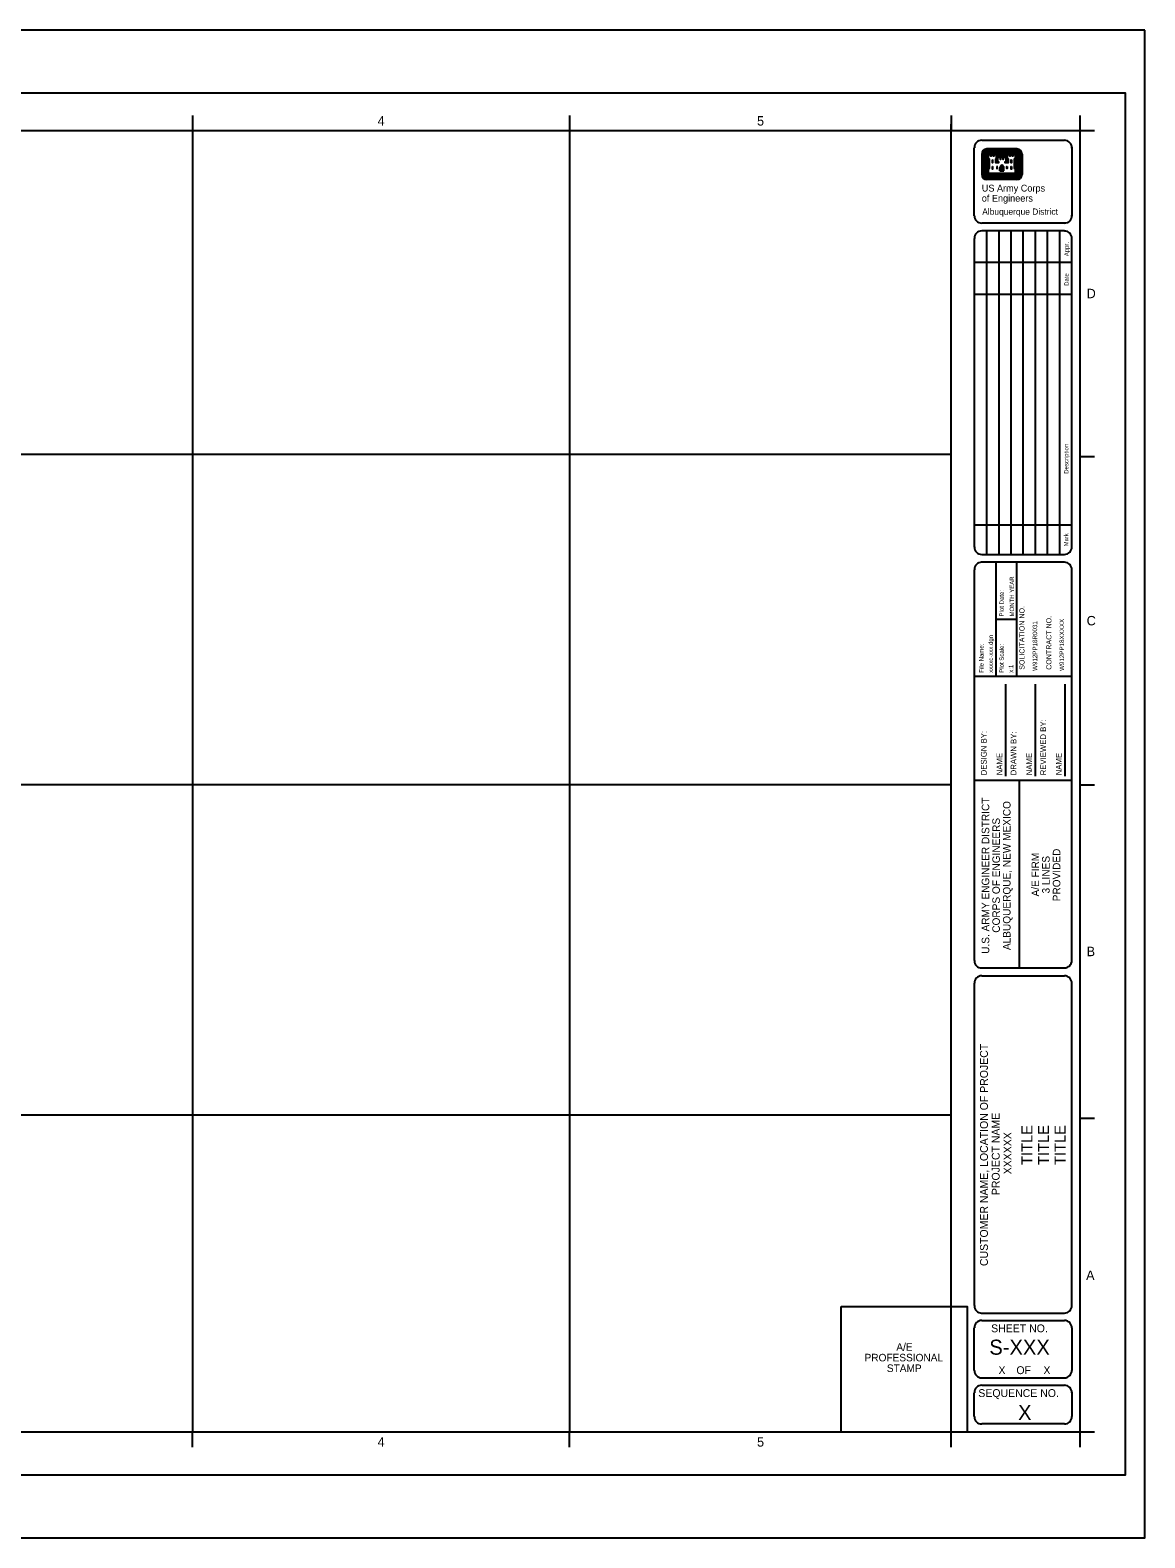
# Model space of a CAD drawing. Extents: x -0.19 to 2.81, y 0.03 to 2.03.
# Drawn here: x 1.329 to 2.806, y 0.032 to 2.032 of the extents above; entities that cross this region are included whole.
import ezdxf

# ---------------------------------------------------------------- set-up
doc = ezdxf.new("R2010")
doc.units = 0
for name, color, linetype in [('G-ANNO-NPLT', 7, 'Continuous'), ('G-ANNO-SYMB', 7, 'Continuous'), ('G-ANNO-TEXT', 7, 'Continuous'), ('G-ANNO-TTBL', 7, 'Continuous'), ('S-ANNO-TEXT', 7, 'Continuous')]:
    doc.layers.add(name, color=color, linetype=linetype)

msp = doc.modelspace()

# ---------------------------------------------------------------- linework, layer by layer
at = {"layer": 'G-ANNO-NPLT'}
for p, q in [((2.5495, 0.1551), (2.5495, 1.9077)), ((1.5442, 1.8993), (1.5442, 0.1724)), ((2.0436, 1.8993), (2.0436, 0.1724)), ((2.5495, 1.4696), (0.0565, 1.4696)), ((2.5495, 1.0314), (0.0565, 1.0314)), ((2.5495, 0.5933), (0.0565, 0.5933))]:
    msp.add_line(p, q, dxfattribs=at)
at = {"layer": 'G-ANNO-SYMB'}
for p, q in [((2.5903, 1.8679), (2.5903, 1.841)), ((2.5906, 1.8679), (2.5906, 1.841)), ((2.5913, 1.8679), (2.5913, 1.841)), ((2.5919, 1.8679), (2.5919, 1.841)), ((2.5923, 1.8679), (2.5923, 1.841)), ((2.5946, 1.8679), (2.5946, 1.841)), ((2.5952, 1.8679), (2.5952, 1.841)), ((2.5959, 1.8679), (2.5959, 1.841)), ((2.5962, 1.8679), (2.5962, 1.841)), ((2.5969, 1.8679), (2.5969, 1.841)), ((2.6366, 1.8748), (2.5972, 1.8748)), ((2.6366, 1.8744), (2.5972, 1.8744)), ((2.6366, 1.8738), (2.5972, 1.8738)), ((2.6366, 1.8731), (2.5972, 1.8731)), ((2.6366, 1.8728), (2.5972, 1.8728)), ((2.6366, 1.8705), (2.5972, 1.8705)), ((2.6366, 1.8698), (2.5972, 1.8698)), ((2.6366, 1.8692), (2.5972, 1.8692)), ((2.6366, 1.8689), (2.5972, 1.8689)), ((2.6366, 1.8682), (2.5972, 1.8682)), ((2.5975, 1.8679), (2.5975, 1.8413)), ((2.5978, 1.8679), (2.5978, 1.842)), ((2.5985, 1.862), (2.5985, 1.8485)), ((2.5991, 1.8616), (2.5991, 1.8492)), ((2.611, 1.8675), (2.6231, 1.8675)), ((2.611, 1.8672), (2.6231, 1.8672)), ((2.611, 1.8666), (2.6231, 1.8666)), ((2.611, 1.8659), (2.6231, 1.8659)), ((2.611, 1.8653), (2.6231, 1.8653)), ((2.611, 1.8649), (2.6231, 1.8649)), ((2.611, 1.8643), (2.6231, 1.8643)), ((2.6349, 1.8616), (2.6349, 1.8492)), ((2.6352, 1.862), (2.6352, 1.8485)), ((2.6359, 1.8679), (2.6359, 1.842)), ((2.6366, 1.8679), (2.6366, 1.8413)), ((2.6369, 1.8679), (2.6369, 1.841)), ((2.6375, 1.8679), (2.6375, 1.841)), ((2.6382, 1.8679), (2.6382, 1.841)), ((2.6385, 1.8679), (2.6385, 1.841)), ((2.6392, 1.8679), (2.6392, 1.841)), ((2.6415, 1.8679), (2.6415, 1.841)), ((2.6421, 1.8679), (2.6421, 1.841)), ((2.6428, 1.8679), (2.6428, 1.841)), ((2.6431, 1.8679), (2.6431, 1.841)), ((2.6438, 1.8679), (2.6438, 1.841)), ((2.6366, 1.8406), (2.5972, 1.8406)), ((2.6366, 1.8403), (2.5972, 1.8403)), ((2.6366, 1.8413), (2.5975, 1.8413)), ((2.6359, 1.842), (2.5978, 1.842)), ((2.6142, 1.8459), (2.6142, 1.8502)), ((2.6142, 1.8459), (2.6195, 1.8459)), ((2.6149, 1.8459), (2.6149, 1.8502)), ((2.6156, 1.8459), (2.6156, 1.8502)), ((2.6159, 1.8459), (2.6159, 1.8502)), ((2.6165, 1.8459), (2.6165, 1.8502)), ((2.6172, 1.8459), (2.6172, 1.8502)), ((2.6179, 1.8459), (2.6179, 1.8502)), ((2.6185, 1.8459), (2.6185, 1.8502)), ((2.6188, 1.8459), (2.6188, 1.8502)), ((2.6195, 1.8459), (2.6195, 1.8502)), ((2.6366, 1.8397), (2.5972, 1.8397)), ((2.6366, 1.839), (2.5972, 1.839)), ((2.6366, 1.8383), (2.5972, 1.8383)), ((2.6366, 1.836), (2.5972, 1.836)), ((2.6366, 1.8357), (2.5972, 1.8357)), ((2.6366, 1.8351), (2.5972, 1.8351)), ((2.6366, 1.8344), (2.5972, 1.8344)), ((2.6366, 1.8341), (2.5972, 1.8341))]:
    msp.add_line(p, q, dxfattribs=at)
for points in [[(2.5985, 1.8679), (2.5985, 1.8626), (2.5995, 1.8616), (2.5995, 1.8492), (2.5985, 1.8479), (2.5985, 1.8423), (2.6356, 1.8423), (2.6356, 1.8479), (2.6343, 1.8492), (2.6343, 1.8616), (2.6356, 1.8626), (2.6356, 1.8679), (2.6306, 1.8679), (2.6267, 1.8679), (2.6234, 1.8679), (2.6234, 1.8626), (2.6244, 1.8616), (2.6244, 1.857), (2.6218, 1.857), (2.6218, 1.8574), (2.6231, 1.8587), (2.6231, 1.8636), (2.6182, 1.8636), (2.6142, 1.8636), (2.611, 1.8636), (2.611, 1.8587), (2.6119, 1.8574), (2.6119, 1.857), (2.6093, 1.857), (2.6093, 1.8616), (2.6106, 1.8626), (2.6106, 1.8679), (2.6057, 1.8679), (2.6018, 1.8679), (2.5985, 1.8679)], [(2.5988, 1.8672), (2.5988, 1.863), (2.6001, 1.8616), (2.6001, 1.8488), (2.5988, 1.8479), (2.5988, 1.8429), (2.6349, 1.8429), (2.6349, 1.8479), (2.6336, 1.8488), (2.6336, 1.8616), (2.6349, 1.863), (2.6349, 1.8672), (2.6313, 1.8672), (2.6313, 1.8653), (2.631, 1.8653), (2.631, 1.8672), (2.6277, 1.8672), (2.6277, 1.8653), (2.6274, 1.8653), (2.6274, 1.8672), (2.6241, 1.8672), (2.6241, 1.863), (2.6251, 1.8616), (2.6251, 1.8564), (2.6211, 1.8564), (2.6211, 1.8577), (2.6224, 1.8587), (2.6224, 1.8633), (2.6188, 1.8633), (2.6188, 1.861), (2.6185, 1.861), (2.6185, 1.8633), (2.6152, 1.8633), (2.6152, 1.861), (2.6149, 1.861), (2.6149, 1.8633), (2.6113, 1.8633), (2.6113, 1.8587), (2.6126, 1.8577), (2.6126, 1.8564), (2.6087, 1.8564), (2.6087, 1.8616), (2.61, 1.863), (2.61, 1.8672), (2.6064, 1.8672), (2.6064, 1.8653), (2.606, 1.8653), (2.606, 1.8672), (2.6028, 1.8672), (2.6028, 1.8653), (2.6024, 1.8653), (2.6024, 1.8672), (2.5988, 1.8672)], [(2.6044, 1.8603), (2.6044, 1.8564), (2.6047, 1.8564), (2.6047, 1.8603), (2.6044, 1.8603)], [(2.6103, 1.8616), (2.61, 1.8613), (2.61, 1.8577), (2.611, 1.8577), (2.6103, 1.8584), (2.6103, 1.8616)], [(2.6238, 1.8616), (2.6241, 1.8613), (2.6241, 1.8577), (2.6228, 1.8577), (2.6234, 1.8584), (2.6234, 1.8616)], [(2.6297, 1.8603), (2.6297, 1.8564), (2.6293, 1.8564), (2.6293, 1.8603), (2.6297, 1.8603)], [(2.6044, 1.8515), (2.6044, 1.8479), (2.6047, 1.8479), (2.6047, 1.8515), (2.6044, 1.8515)], [(2.6103, 1.8515), (2.6103, 1.8488), (2.6106, 1.8488), (2.6106, 1.8515), (2.6103, 1.8515)], [(2.6238, 1.8515), (2.6238, 1.8488), (2.6234, 1.8488), (2.6234, 1.8515), (2.6238, 1.8515)], [(2.6297, 1.8515), (2.6297, 1.8479), (2.6293, 1.8479), (2.6293, 1.8515), (2.6297, 1.8515)]]:
    msp.add_lwpolyline(points, dxfattribs=at)
for centre, radius, start, end in [((2.5972, 1.8678), 0.00696, 90, 180), ((2.5972, 1.8678), 0.00656, 90, 180), ((2.5972, 1.8678), 0.006, 90, 180), ((2.5972, 1.8678), 0.00543, 90, 180), ((2.5972, 1.8678), 0.00487, 90, 180), ((2.5972, 1.8678), 0.00261, 90, 180), ((2.5972, 1.8678), 0.00205, 90, 180), ((2.5972, 1.8678), 0.00148, 90, 180), ((2.5972, 1.8678), 0.000919, 90, 180), ((2.5972, 1.8678), 0.000355, 90, 180), ((2.6367, 1.8678), 0.00696, 0, 90), ((2.6367, 1.8678), 0.00656, 0, 90), ((2.6367, 1.8678), 0.006, 0, 90), ((2.6367, 1.8678), 0.00543, 0, 90), ((2.6367, 1.8678), 0.00487, 0, 90), ((2.6367, 1.8678), 0.00261, 0, 90), ((2.6367, 1.8678), 0.00205, 0, 90), ((2.6367, 1.8678), 0.00148, 0, 90), ((2.6367, 1.8678), 0.000919, 0, 90), ((2.6367, 1.8678), 0.000355, 0, 90), ((2.5972, 1.8411), 0.00696, 180, 270), ((2.5972, 1.8411), 0.00656, 180, 270), ((2.5972, 1.8411), 0.006, 180, 270), ((2.5972, 1.8411), 0.00543, 180, 270), ((2.5972, 1.8411), 0.00487, 180, 270), ((2.5972, 1.8411), 0.00261, 180, 270), ((2.5972, 1.8411), 0.00205, 180, 270), ((2.5972, 1.8411), 0.00148, 180, 270), ((2.5972, 1.8411), 0.000919, 180, 270), ((2.5972, 1.8411), 0.000355, 180, 270), ((2.6179, 1.8498), 0.00361, 105.6681, 176.0575), ((2.6179, 1.8498), 0.00305, 103.4698, 176.0575), ((2.6179, 1.8498), 0.00248, 103.4698, 176.0575), ((2.6179, 1.8498), 0.00192, 103.4698, 176.0575), ((2.616, 1.8498), 0.00135, 3.9425, 76.5302), ((2.616, 1.8498), 0.00192, 3.9425, 76.5302), ((2.616, 1.8498), 0.00248, 3.9425, 76.5302), ((2.6179, 1.8498), 0.00135, 103.4698, 176.0575), ((2.616, 1.8498), 0.00305, 3.9425, 76.5302), ((2.616, 1.8498), 0.00361, 3.9425, 74.3949), ((2.6367, 1.8411), 0.00696, 270, 0), ((2.6367, 1.8411), 0.00261, 270, 0), ((2.6367, 1.8411), 0.00205, 270, 0), ((2.6367, 1.8411), 0.00148, 270, 0), ((2.6367, 1.8411), 0.000919, 270, 0), ((2.6367, 1.8411), 0.000355, 270, 0), ((2.6367, 1.8411), 0.00487, 270, 360), ((2.6367, 1.8411), 0.00543, 270, 360), ((2.6367, 1.8411), 0.006, 270, 360), ((2.6367, 1.8411), 0.00656, 270, 360)]:
    msp.add_arc(centre, radius, start, end, dxfattribs=at)
at = {"layer": 'G-ANNO-TEXT'}
msp.add_line((2.6362, 1.2506), (2.609, 1.2506), dxfattribs=at)
at = {"layer": 'G-ANNO-TTBL'}
for p, q in [((1.5442, 1.919), (1.5442, 1.8993)), ((2.0436, 1.919), (2.0436, 1.8993)), ((2.5495, 1.919), (2.5495, 1.8993)), ((2.7202, 1.919), (2.7202, 0.1527)), ((0.0368, 1.8993), (2.7398, 1.8993)), ((2.5804, 1.7247), (2.7097, 1.7247)), ((2.5804, 1.682), (2.7097, 1.682)), ((2.7202, 1.4667), (2.7398, 1.4667)), ((2.5804, 1.3763), (2.7097, 1.3763)), ((2.609, 1.3265), (2.609, 1.1751)), ((2.6362, 1.3265), (2.6362, 1.1751)), ((2.7097, 1.1751), (2.5804, 1.1751)), ((2.6221, 1.0428), (2.6221, 1.1647)), ((2.6614, 1.0428), (2.6614, 1.1647)), ((2.7008, 1.0428), (2.7008, 1.1647)), ((2.7097, 1.0371), (2.5804, 1.0371)), ((2.6399, 1.0371), (2.6399, 0.7884)), ((2.7202, 1.0314), (2.7398, 1.0314)), ((2.7202, 0.5891), (2.7398, 0.5891)), ((2.7398, 0.1724), (0.0368, 0.1724)), ((1.5442, 0.1527), (1.5442, 0.1724)), ((2.0436, 0.1527), (2.0436, 0.1724)), ((2.5495, 0.1527), (2.5495, 0.1724))]:
    msp.add_line(p, q, dxfattribs=at)
for points in [[(2.8064, 2.0324), (-0.1936, 2.0324), (-0.1936, 0.0324), (2.8064, 0.0324)], [(-0.053, 1.9491), (2.7804, 1.9491), (2.7804, 0.1157), (-0.053, 0.1157)], [(2.4041, 0.3391), (2.5708, 0.3391), (2.5708, 0.1724), (2.4041, 0.1724)]]:
    msp.add_lwpolyline(points, close=True, dxfattribs=at)
for points in [[(2.5903, 1.8863), (2.6999, 1.8863)], [(2.5804, 1.7863), (2.5804, 1.8764)], [(2.7097, 1.877), (2.7097, 1.7857)], [(2.7006, 1.7765), (2.5903, 1.7765)], [(2.6999, 1.7661), (2.5903, 1.7661)], [(2.5966, 1.7661), (2.5966, 1.3369)], [(2.6127, 1.7661), (2.6127, 1.3369)], [(2.6288, 1.7661), (2.6288, 1.3369)], [(2.6449, 1.7661), (2.6449, 1.3369)], [(2.661, 1.7661), (2.661, 1.3369)], [(2.6771, 1.7661), (2.6771, 1.3369)], [(2.6932, 1.7661), (2.6932, 1.3369)], [(2.5804, 1.7562), (2.5804, 1.3467)], [(2.7097, 1.3461), (2.7097, 1.7562)], [(2.6999, 1.3265), (2.5894, 1.3265)], [(2.5903, 1.3369), (2.6999, 1.3369)], [(2.5804, 1.3167), (2.5804, 0.7982)], [(2.7097, 0.7982), (2.7097, 1.3167)], [(2.5903, 0.7884), (2.6999, 0.7884)], [(2.5804, 0.7681), (2.5804, 0.3404)], [(2.5903, 0.778), (2.6999, 0.778)], [(2.7097, 0.3408), (2.7097, 0.7681)], [(2.5896, 0.3306), (2.6999, 0.3306)], [(2.5903, 0.3207), (2.6999, 0.3207)], [(2.5804, 0.2545), (2.5804, 0.3109)], [(2.7097, 0.3109), (2.7097, 0.2545)], [(2.5903, 0.2446), (2.6999, 0.2446)], [(2.5804, 0.1933), (2.5804, 0.2249)], [(2.5903, 0.2348), (2.6999, 0.2348)], [(2.7097, 0.2255), (2.7097, 0.1933)], [(2.6999, 0.1835), (2.5903, 0.1835)]]:
    msp.add_lwpolyline(points, dxfattribs=at)
for centre, start, end in [((2.5903, 1.8764), 90, 180), ((2.6999, 1.8764), 356.3757, 90), ((2.5903, 1.7863), 180, 270), ((2.6999, 1.7863), 270, 3.6243), ((2.5903, 1.7562), 90, 180), ((2.6999, 1.7561), 0, 90), ((2.5903, 1.3468), 180, 270), ((2.6999, 1.3467), 270, 0), ((2.5903, 1.3167), 90, 180), ((2.6999, 1.3167), 0, 90), ((2.5903, 0.7982), 180, 270), ((2.6999, 0.7983), 270, 0), ((2.5903, 0.7681), 90, 180), ((2.6999, 0.7681), 0, 90), ((2.5903, 0.3404), 180, 270), ((2.6999, 0.3404), 270, 0), ((2.5903, 0.3109), 90, 180), ((2.6999, 0.3109), 0, 90), ((2.5903, 0.2545), 180, 270), ((2.6999, 0.2545), 270, 0), ((2.5903, 0.2249), 90, 180), ((2.6999, 0.2249), 0, 90), ((2.5903, 0.1933), 180, 270), ((2.6999, 0.1933), 270, 0)]:
    msp.add_arc(centre, 0.00984, start, end, dxfattribs=at)
at = {"layer": 'S-ANNO-TEXT'}
msp.add_circle((2.7804, 0.1157), 0.0000168, dxfattribs=at)

# ---------------------------------------------------------------- texts
at = {"layer": 'G-ANNO-TEXT'}
for s, height, p in [('4', 0.0125, (1.7894, 1.9058)), ('5', 0.0125, (2.2924, 1.9058)), ('US Army Corps', 0.009029, (2.5903, 1.8183)), ('of Engineers', 0.009029, (2.5903, 1.8049)), ('Albuquerque District', 0.00833, (2.5909, 1.7875)), ('D', 0.0125, (2.7293, 1.6768)), ('C', 0.0125, (2.7293, 1.2428)), ('B', 0.0125, (2.7293, 0.804)), ('A', 0.0125, (2.7286, 0.3745)), ('SHEET NO.', 0.01042, (2.6027, 0.3051)), ('A/E ', 0.01, (2.477, 0.2806)), ('PROFESSIONAL', 0.01, (2.4349, 0.2665)), ('STAMP', 0.01, (2.4645, 0.2524)), ('OF', 0.01042, (2.6362, 0.2496)), ('SEQUENCE NO.', 0.010417, (2.5857, 0.2192)), ('4', 0.0125, (1.7894, 0.1534)), ('5', 0.0125, (2.2924, 0.1534))]:
    msp.add_text(s, height=height, dxfattribs=at).set_placement(p)
for s, height, p in [('Appr.', 0.00574, (2.7055, 1.7325)), ('Date', 0.00574, (2.7055, 1.6932)), ('Description', 0.005741, (2.7051, 1.4439)), ('Mark', 0.00558, (2.7048, 1.3478)), ('MONTH YEAR', 0.00578, (2.6331, 1.2546)), ('Plot Date:', 0.00579, (2.6195, 1.2546)), ('SOLICITATION NO.', 0.006809, (2.6469, 1.1839)), ('W912PP18R0031', 0.005968, (2.6637, 1.1824)), ('CONTRACT NO.', 0.006809, (2.6826, 1.1839)), ('W912PP18XXXXX', 0.005968, (2.6993, 1.1824)), ('File Name:', 0.00579, (2.5926, 1.18)), ('Plot Scale:', 0.005785, (2.6195, 1.18)), ('DESIGN BY:', 0.00769, (2.5968, 1.0439)), ('DRAWN BY:', 0.00768, (2.6362, 1.0439)), ('REVIEWED BY:', 0.007687, (2.6755, 1.0439)), ('U.S. ARMY ENGINEER DISTRICT', 0.01, (2.6002, 0.8071)), ('ALBUQUERQUE, NEW MEXICO', 0.01, (2.6284, 0.8121)), ('CORPS OF ENGINEERS', 0.01, (2.6143, 0.8351)), ('A/E FIRM', 0.01, (2.6662, 0.8832)), ('PROVIDED', 0.01, (2.6944, 0.8768)), ('3 LINES', 0.01, (2.6803, 0.8872)), ('CUSTOMER NAME, LOCATION OF PROJECT', 0.010417, (2.5984, 0.3929)), ('PROJECT NAME', 0.010417, (2.614, 0.4871)), ('XXXXXX', 0.01042, (2.6296, 0.5147))]:
    msp.add_text(s, height=height, rotation=90, dxfattribs=at).set_placement(p)
at = {"layer": 'S-ANNO-TEXT'}
for s, height, p in [('xxxxc-xxx.dgn', 0.005785, (2.605, 1.18)), ('x:1', 0.00579, (2.6319, 1.18)), ('NAME', 0.00769, (2.6175, 1.0439)), ('NAME', 0.00768, (2.6569, 1.0439)), ('NAME', 0.00769, (2.6962, 1.0439)), ('TITLE', 0.01458, (2.6575, 0.527)), ('TITLE', 0.01458, (2.6794, 0.527)), ('TITLE', 0.01458, (2.7013, 0.527))]:
    msp.add_text(s, height=height, rotation=90, dxfattribs=at).set_placement(p)
for s, height, p in [('S-XXX', 0.01997, (2.6003, 0.2753)), ('X', 0.0104, (2.6124, 0.2496)), ('X', 0.0104, (2.672, 0.2496)), ('X', 0.02, (2.6384, 0.1887))]:
    msp.add_text(s, height=height, dxfattribs=at).set_placement(p)

doc.saveas('drawing.dxf')
